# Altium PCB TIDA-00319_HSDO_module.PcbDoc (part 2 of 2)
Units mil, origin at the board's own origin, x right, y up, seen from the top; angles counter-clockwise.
Board outline 6250 x 2150 mil, 2 copper layers (Component Side, Bottom Layer), stack 12.8 mil thick; 90 components, 121 nets, 306 pads, 593 vias.
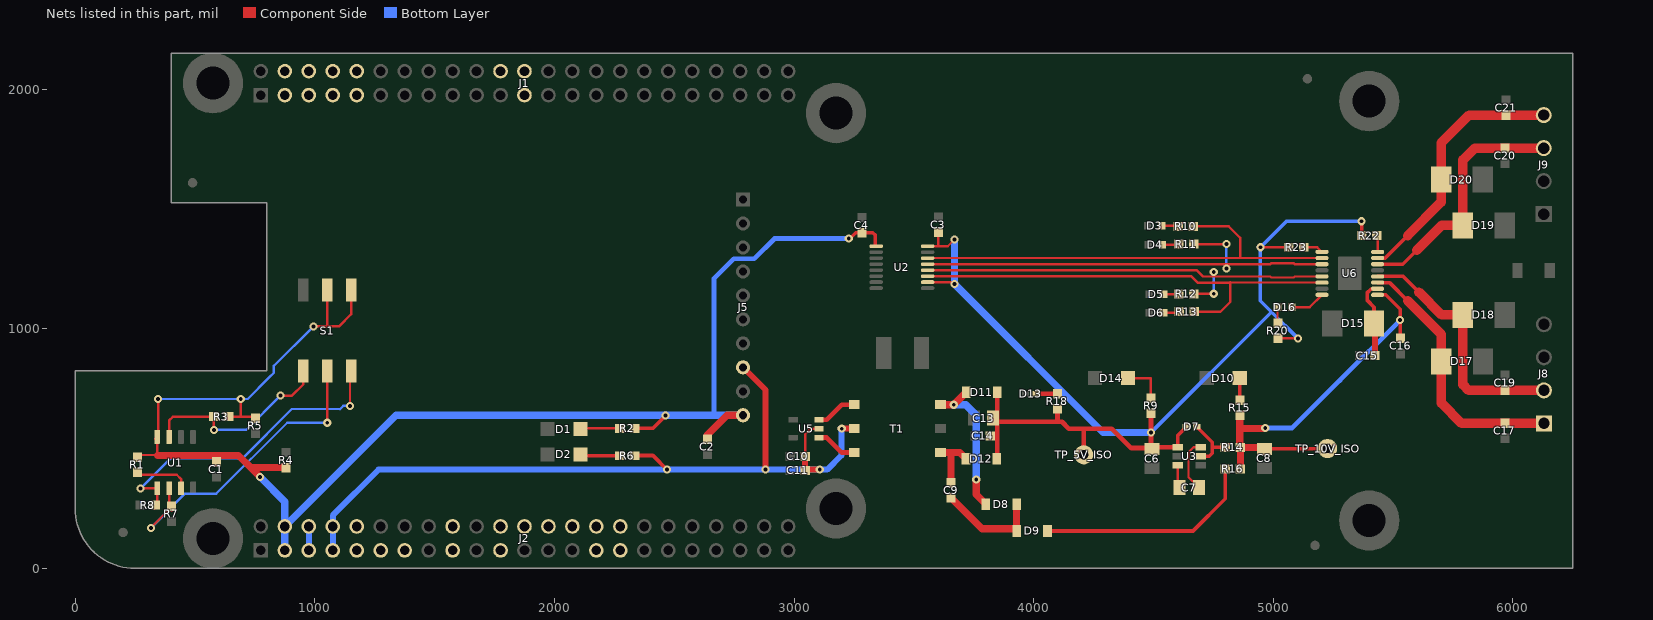
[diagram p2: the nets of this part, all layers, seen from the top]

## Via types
v1: diameter 20, hole 8, Component Side to Bottom Layer, tented both sides, 517 vias
v2: diameter 39.37, hole 19.68, Component Side to Bottom Layer, 36 vias
v3: diameter 34, hole 16, Component Side to Bottom Layer, 32 vias
v4: diameter 19.68, hole 7.87, Component Side to Bottom Layer, 6 vias
v5: diameter 50, hole 28, Component Side to Bottom Layer, 2 vias

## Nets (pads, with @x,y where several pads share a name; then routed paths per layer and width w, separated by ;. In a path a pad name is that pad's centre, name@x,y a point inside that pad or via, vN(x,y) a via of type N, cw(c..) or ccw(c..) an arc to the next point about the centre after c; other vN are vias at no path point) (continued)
MMC1_DAT1: J1.24
MMC1_DAT2: J1.5
MMC1_DAT3: J1.6
MMC1_DAT4: J1.23
MMC1_DAT5: J1.22
MMC1_DAT6: J1.3
MMC1_DAT7: J1.4
NetC7_1: C7.1 U3.6 | length 224.3
  Component Side w10: C7.1@4689,337 4646,380 4646,484.69 4666.72,505.4 U3.6@4696.24,505.4
NetC7_2: C7.2 U3.3 | length 96.6
  Component Side w10: U3.3@4601.76,430.6 4601.76,344.24 C7.2@4609,337
NetC9_1: C9.1 D8.1 D9.2 | length 443.3
  Component Side w30: C9.1@3655,294.5 3784.5,165 3919.53,165 D9.2@3928.53,156 3928.53,267.06 D8.1@3929.47,268
NetC15_1: C15.1 D15.1 U6.2 | length 325.2
  Component Side w15: D15.1@5420.01,1022 5420.01,1090.15 5392.58,1117.57 5392.58,1151.32 5406.56,1165.29 5424.55,1165.29 5426.28,1167.02 U6.2@5435.14,1167.02
  Component Side w25: D15.1@5420.01,1022 5423.5,1018.51 C15.1@5423.5,888
NetC17_1: C17.1 D17.1 J8.1 U6.3 | length 1105
  Component Side w15: U6.3@5435.14,1192.61 5484.39,1192.61 5561,1116
  Component Side w40: 5561,1116 5700.99,976.01 D17.1@5700.99,864 5700.99,690.01 5785.8,605.2 J8.1@6129.3,605.2
NetC19_1: C19.1 D18.1 J8.2 U6.4 | length 1061.5
  Component Side w15: U6.4@5435.14,1218.2 5541.8,1218.2 5607,1153
  Component Side w40: 5607,1153 5702,1058 D18.1@5790.99,1058 5790.99,767.01 5815,743 J8.2@6129.3,743
NetC20_1: C20.1 D19.1 J9.3 U6.6 | length 1053.7
  Component Side w15: U6.6@5435.14,1269.39 5540.39,1269.39 5598,1327
  Component Side w40: 5598,1327 5702,1431 D19.1@5790.99,1431 5790.99,1703.99 5840.8,1753.8 J9.3@6128.3,1753.8
NetC21_1: C21.1 D20.1 J9.4 U6.7 | length 1087.8
  Component Side w15: U6.7@5435.14,1294.98 5466.98,1294.98 5562,1390
  Component Side w40: 5560,1388 5699.99,1527.99 D20.1@5699.99,1622 5699.99,1774.99 5816.59,1891.59 J9.4@6128.3,1891.59
NetD1_2: D1.2 R2.1 | length 136.8
  Component Side w10: D1.2@2108.53,581.32 D1.2@2111.53,584.32 ; 2139.9,584 R2.1@2272.5,584
NetD2_2: D2.2 R6.1 | length 137.7
  Component Side w15: D2.2@2108.53,475.32 D2.2@2113.53,470.32 ; 2141.9,470 R6.1@2272.5,470
NetD3_1: D3.1 R10.1 | length 69.8
  Component Side w10: D3.1@4534.53,1429 4601.5,1429 R10.1@4603.5,1427
NetD4_1: D4.1 R11.1 | length 68.8
  Component Side w10: D4.1@4536.53,1351 4602.5,1351 R11.1@4604.5,1353
NetD5_1: D5.1 R12.1 | length 62.4
  Component Side w10: D5.1@4542.53,1144 4603.5,1144 R12.1@4604.5,1145
NetD6_1: D6.1 R13.1 | length 64.6
  Component Side w10: D6.1@4543.53,1067 4602.5,1067 R13.1@4606.5,1071
NetD7_1: D7.1 R14.1 U3.5 | length 246.3
  Component Side w15: D7.1@4680.65,591 4745,526.65 4745,506 ; U3.5@4696.24,468 4733,468 4745,480 4745,506 ; R14.1@4799.5,505 4746,505 4745,506
NetD9_1: D9.1 R16.1 | length 922.2
  Component Side w15: D9.1@4057.47,156 4665,156 4799.5,290.5 R16.1@4799.5,415
NetD10_2: D10.2 R15.1 | length 91.5
  Component Side w15: D10.2@4859.9,794 4860,793.9 R15.1@4860,702.5
NetD13_1: D13.1 R18.1 | length 89.6
  Component Side w20: D13.1@4009.65,729 4098.5,729 R18.1@4099,729.5
NetD14_2: D14.2 R9.1 | length 183.6
  Component Side w10: D14.2@4392.9,794 4489,794 R9.1@4489,706.5
NetD16_1: D16.1 R20.2 | length 68.1
  Component Side w10: D16.1@5017.47,1090 5017.47,1024.02 R20.2@5019,1022.5
NetD16_2: D16.2 U6.16 | length 147.6
  Component Side w10: D16.2@5076.53,1090 5151.43,1090 U6.16@5202.86,1141.43
NetR1_1: R1.1 U1.3 | length 211.2
  Component Side w10: R1.1@277.5,391 424,391 442,373 U1.3@442,333.72
NetR3_1: R3.1 S1.1 U1.7 | length 823.5
  Component Side w10: U1.7@392,548.28 392,617 408,633 R3.1@578.5,633 578.5,578.5 v3(579,578) ; v3(857,721) 905,721 952,768 S1.1@952,822.71
  Bottom Layer w10: v3(579,578) 714,578 v3(857,721)
NetR7_2: R7.2 S1.2 U1.2 | length 1336.9
  Component Side w10: v3@320,173.65 R7.2@395,248.65 ; U1.2@392,333.72 392,257.5 403,246.5 R7.2@403,241 ; v3(1052,608) S1.2@1052,822.71
  Bottom Layer w10: v3(316,168) 458,312 589,312 885,608 v3(1052,608)
NetR8_2: R8.2 S1.3 U1.1 | length 1319.7
  Component Side w10: v3(273.28,333.72) U1.1@342,333.72 342,261.5 R8.2@331.5,251 ; v3(1147,678) 1147,817.71 1150,820.71 S1.3@1152,822.71
  Bottom Layer w10: v3(273.28,333.72) 398.57,459 698,459 904,665 1104,665 1105,664 1119,678 v3(1147,678)
NetR22_1: R22.1 U6.8 | length 72.4
  Component Side w10: R22.1@5431.5,1388.98 5436.14,1384.34 U6.8@5436.14,1318.55
NetR23_1: R23.1 U6.9 | length 86.2
  Component Side w10: R23.1@5126.5,1339.98 5182.43,1339.98 U6.9@5203.86,1318.55
NetT1_1: T1.1 U5.3 | length 172.8
  Component Side w20: U5.3@3104.13,620.4 3136.4,620.4 3199,683 T1.1@3251,683
NetT1_3: T1.3 U5.1 | length 172.8
  Component Side w20: U5.1@3104.13,545.6 3136.6,545.6 3199.2,483 T1.3@3251,483
OUTA: R13.2 U2.11 U6.14 | length 1905
  Component Side w10: U2.11@3557.28,1219.5 4656.5,1219.5 4683.39,1192.61 4820,1192.61 4820,1112 4779,1071 R13.2@4669.5,1071 ; 4819.86,1193.23 U6.14@5202.86,1192.61
OUTB: R12.2 U2.12 U6.13 | length 1853.7
  Component Side w10: U2.12@3557.28,1244.5 4679.5,1244.5 4705.8,1218.2 4751,1218.2 ; R12.2@4667.5,1145 4668.5,1146 v3(4751,1146) ; v3(4751,1237) 4751,1218.2 ; U6.13@5202.86,1218.2 5089.33,1218.2 5085.13,1214 4991.28,1214 4987.08,1218.2 4751,1218.2
  Bottom Layer w10: v3(4751,1146) v3(4751,1237)
OUTC: R11.2 U2.13 U6.11 | length 1951.8
  Component Side w10: U2.13@3557.28,1269.5 4804,1269.5 v3(4804,1251) ; R11.2@4667.5,1364 4678.5,1353 v3(4804,1353) ; 4764.86,1269.48 4987.17,1269.48 4991.69,1274 5084.72,1274 5089.24,1269.48 U6.11@5203.36,1269.48 ; U6.11@5187.5,1267.48 5188,1266.98 U6.11@5188.39,1267.37
  Bottom Layer w10: v3(4804,1251) v3(4804,1353)
OUTD: R10.2 U2.14 U6.10 | length 1972.2
  Component Side w10: U2.14@3569.22,1295 4862,1295 4862,1379 4814,1427 R10.2@4666.5,1427 ; 4822.86,1294.98 U6.10@5202.86,1294.98
PWR_BUT: J2.9
SPI0_CS: J2.17
SPI0_D0: J2.21
SPI0_D1: J2.18
SPI0_SCLK: J2.22
SPI1_CS0: J2.28
SPI1_D0: J2.29
SPI1_D1: J2.30
SPI1_SCLK: J2.31
SYS_5V: C10.1 C11.1 J2.7 J2.8 J5.8 R6.2 T1.2 U5.2 | length 3449.7
  Component Side w10: C10.1@3046.5,467 3046.5,559.81 3069.69,583 U5.2@3104.13,583
  Component Side w15: R6.2@2335.5,470 2336.5,471 2411,471 v3(2470,412)
  Component Side w25: J5.8@2787,839 2881,745 v3(2881,412) ; C10.1@3046.5,467 C11.1@3046.5,409 3049.5,412 v3(3107,412) ; v3@3193,583 T1.2@3251,583
  Bottom Layer w15: v3(2470,412) v3@2480,412
  Bottom Layer w25: J2.7@1075,75 J2.8@1075,175 1075,221 1266,412 v3(2470,412) ; v3@2480,412 v3(2881,412) v3(3107,412) 3138,412 3198,472 3198,580 v3@3194,584
  other v3: 3199,583
SYS_RESETN: J2.10
TIMER4: J1.7
TIMER5: J1.9
TIMER6: J1.10
TIMER7: J1.8
TR_N: C9.2 D12.2 T1.4 | length 246.1
  Component Side w30: T1.4@3611,483 3663,483 ; C9.2@3655,357.5 3655,475 3663,483 ; D12.2@3717.53,457 3691.53,483 3663,483
TR_P: D8.2 D11.2 T1.6 | length 628.6
  Component Side w30: T1.6@3611,683 v3(3666.53,683) D11.2@3718.53,735 ; v3(3760,371) 3760,308.53 D8.2@3800.53,268
  Bottom Layer w30: v3(3666.53,683) 3716,683 3760,639 v3(3760,371)
UART1_RXD: J2.26
UART1_TXD: J2.24
UART4_RXD: J2.11
UART4_TXD: J2.13
VDD_3V3B: C1.1 C2.1 C4.2 J2.3 J2.4 J5.10 R1.2 R2.2 R3.2 R4.2 R5.2 S1.4 S1.5 U1.8 U2.1 | length 6509.9
  Component Side w10: R1.2@271,473 342,472.5 ; U1.8@334.22,540.5 U1.8@342,548.28 ; 343,471.5 342,472.5 ; v3(346,707) 346,552.28 U1.8@342,548.28 ; R3.2@641.5,633 691,633 ; v3(691,707) 691,633 ; R5.2@752,626.5 745.5,633 691,633 ; v3(994,1010) 1101,1010 1152,1061 S1.4@1152,1161.29 ; 1052,1016 S1.5@1052,1161.29 ; 342,472.5 U1.8@342,548.28
  Component Side w15: R2.2@2335.5,584 2410,584 v3(2464,638) ; v3(3228.29,1376.29) 3228.29,1371.71 3257.78,1401.2 C4.2@3282.57,1401.2 3328.8,1401.2 3338,1392 3338,1349.22 U2.1@3342.72,1344.5
  Component Side w30: 343,471.5 681.5,471.5 732.5,420.5 ; v3(771,382) 732.5,420.5 ; R4.2@880,420.5 732.5,420.5 ; C2.1@2636,554.5 2720.5,639 J5.10@2787,639
  Bottom Layer w10: v3(346,707) v3(691,707) 720,707 809,796 809.08,796 829,815.92 829,845 v3(994,1010)
  Bottom Layer w15: v3(2464,638) v3@2464,639
  Bottom Layer w20: 2666,639 2666,1210 2747.97,1291.97 2834.03,1291.97 2918.34,1376.29 v3(3228.29,1376.29)
  Bottom Layer w30: v3(771,382) 875,278 J2.4@875,175 ; J2.3@875,75 J2.4@875,175 ; J5.10@2787,639 2666,639 2464,639 1339,639 J2.4@875,175 ; v3(3228.29,1376.29) v3@3229.53,1376.31
VDD_5V: J2.5 J2.6 | length 100
  Bottom Layer w25: J2.5@975,75 J2.6@975,175
VDD_5V_ISO: C3.2 C6.1 C13.1 C14.1 D7.2 D11.1 D12.1 R9.2 R18.2 R20.1 R22.2 R23.2 TP_5V_ISO.1 U2.10 U2.16 U3.1 | length 4945.4
  Component Side w10: U2.10@3557.28,1194.5 3661.5,1194.5 v3(3670,1186) ; U2.16@3557.28,1344.5 3601,1344.5 ; C3.2@3602,1399 3602,1345.5 3601,1344.5 ; v3(3670,1373) 3641.5,1344.5 3601,1344.5 ; D12.1@3847.47,475 3848.47,474 D12.1@3851.5,470.96 ; v3(4946.02,1339.98) R23.2@5063.5,1339.98 ; R20.1@5019,959.5 v3(5102.5,959.5)
  Component Side w15: U3.1@4601.76,505.4 4601.76,555.41 D7.2@4637.35,591 ; R22.2@5368.5,1388.98 v3(5368.5,1448.5)
  Component Side w20: C13.1@3846,612 4099,612 ; D12.1@3846.47,457 3848.47,459 D12.1@3848.47,474 ; D12.1@3847.47,475 D11.1@3847.47,735 ; R18.2@4099,666.5 4099,612 ; 4117,612 4099,612 ; 4118,612 4147,583 4209,583 ; TP_5V_ISO.1@4209,474 4209,583 ; R9.2@4490,646.5 4490,566 C6.1@4490,505.4 ; C6.1@4494,498 C6.1@4490,502 ; U3.1@4601.76,505.4 C6.1@4490,505.4 ; 4209,583 4326,583 4407,502 C6.1@4490,502 ; C6.1@4490,502 C6.1@4490,505.4
  Component Side w30: v3(4489,567) v3@4490,566
  Bottom Layer w15: v3@4945,1341 4945,1117 4991,1071 v3(5102.5,959.5) ; v3(4946.02,1339.98) 5054.53,1448.5 v3(5368.5,1448.5)
  Bottom Layer w16: v3(4489,567) 4991,1069 4991,1071
  Bottom Layer w30: v3(3670,1373) v3(3670,1186) 4289,567 v3(4489,567) ; v3@4945,1341 v3(4946.02,1339.98)
VDD_10V_ISO: C8.1 C16.1 R14.2 R15.2 R16.2 TP_10V_ISO.1 U6.1 | length 1689.4
  Component Side w14: C16.1@5529,961.5 C16.1@5531,959.5 ; v3(5529,1036) 5529,1068
  Component Side w15: C8.1@4963,499 TP_10V_ISO.1@5225,499 ; U6.1@5435.14,1141.43 5468.57,1141.43 5529,1081 5529,1068 ; C16.1@5529,961.5 v3(5529,1036)
  Component Side w30: R15.2@4860,639.5 4860,584 ; R16.2@4862.5,415 R14.2@4862.5,505 ; C8.1@4963,499 4957,505 R14.2@4862.5,505 ; v3(4966,586) 4964,584 4860,584 ; TP_10V_ISO.1@5225,499 TP_10V_ISO.1@5226,500 ; 4860,584 4860,507.5 R14.2@4862.5,505
  Bottom Layer w20: v3(4966,586) 5079,586 5277.5,784.5 v3(5529,1036)
VDD_ADC: J2.32
pads on no net: FID1.1 FID2.1 FID4.1 FID5.1 MH1.1 MH2.1 MH3.1 MH4.1 MH5.1 MH6.1 U2.7 U6.15
copper on no net:
  other v2: 575,27.56 490.61,76.28 659.39,76.28 5400,102.56 5315.61,151.28 5484.39,151.28 3175,152.56 490.61,173.72 659.39,173.72 3090.61,201.28 3259.39,201.28 575,222.44 5315.61,248.72 5484.39,248.72 5400,297.44 3090.61,298.72 3259.39,298.72 3175,347.44 3175,1802.56 3090.61,1851.28 3259.39,1851.28 5400,1852.56 5315.61,1901.28 5484.39,1901.28 575,1927.56 3090.61,1948.72 3259.39,1948.72 490.61,1976.28 659.39,1976.28 3175,1997.44 5315.61,1998.72 5484.39,1998.72 5400,2047.44 490.61,2073.72 659.39,2073.72 575,2122.44

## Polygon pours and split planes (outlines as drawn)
DGND on Bottom Layer "Bottom Layer-DGND" (solid, remove dead copper, pour order 43): 20,2130 20,20 3370,20 3370,2130
GND_ISO on Bottom Layer "Bottom-GND_Signal" (solid, remove dead copper, pour order 59): 3540,0 3540,2150 6249.98,2150 6249.98,0
GND_ISO on Component Side "Top-GND_Signal" (solid, remove dead copper, pour order 60): 3540,0 3540,2150 6250,2150 6250,0
DGND on Component Side "DGND_TL" (solid, remove dead copper, pour order 81): 3370,2150 400,2150 0,2150 0,0 3370,0

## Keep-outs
Keep-Out Layer:
  lines w10: -5,825 -5,250 ccw(c250,250) 250,-5 6250,-5 ; 0,830 795,830 795,1520 400,1520 ; 6250,2155 400,2155 ; 6255,2150 6255,0 ; 395,1525 ccw(c400,1525) 400,1520 ; 395,1525 ccw(c400,1525) 400,1520 ; 395,1525 395,2150 ; 395,2150 cw(c400,2150) 400,2155 ; 395,2150 cw(c400,2150) 400,2155 ; 6250,-5 ccw(c6250,0) 6255,0 ; 6250,-5 ccw(c6250,0) 6255,0 ; 7517,2166 cw(c7517,2161) 7522,2161 ccw(c7517,2161) 7517,2166
  text ".Layer_Name" at 577,-858.49 h60

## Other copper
Component Side:
  rectangle net EARTH: 6096,1381.75 6201,1513
  rectangle net EARTH: 6095,984 6201,1113
  rectangle net EARTH: 6126,1082 6201,1407
  region net NetC15_1: 5385,1131.98 5385,1074 5427,1074
  text ".CopyrightYear" at 1455,1453 h60
  text ".Layer_Name" at 577,-858.49 h60
Bottom Layer:
  text ".Layer_Name" at 577,-858.49 h60

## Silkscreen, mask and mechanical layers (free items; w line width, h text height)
Top Overlay:
  region: 1397,1530 1097,1530 1097,1430 1397,1430
  lines w5: 5869,1509.5 5870,1510.5
  text "P8-Header" at 2140,1830 h40
  text ".PRJ_Number" at 892,1566 h60
  text ".PCB_Rev" at 912,1459 h60
  text "-" at 1029,1453 h60
  text "In4" at 2598,1418 h60
  text "OUT4" at 4137,1406 h60
  text "OUT3" at 4137,1340 h60
  text "In3" at 2598,1327 h60
  text "WR" at 892,1237 h30
  text "A1" at 1031,1235 h30
  text "A0" at 1172,1235 h30
  text "In2" at 2598,1129 h60
  text "OUT2" at 4137,1108 h60
  text "Fault" at 4834,1074 h60
  text "OUT1" at 4137,1039 h60
  text "In1" at 2598,1022 h60
  text "5V ISO" at 4195,868 h60
  text "10V ISO" at 4662,865 h60
  text "5V" at 2589,809 h60
  text "3.3V" at 2543,619 h60
  text "3.3V" at 1733.63,562.32 h40
  text "5V" at 1804.63,461.32 h40
  text "P9-Header" at 2140,260 h40
  text ".Layer_Name" at 577,-858.49 h60
Bottom Overlay:
  text ".Layer_Name" at 577,-858.49 h60
Top Paste:
  text ".Layer_Name" at 577,-858.49 h60
Bottom Paste:
  text ".Layer_Name" at 577,-858.49 h60
Top Solder:
  text ".Layer_Name" at 577,-858.49 h60
  text ".Layer_Name" at 577,-858.49 h60
Solder Side:
  text ".Layer_Name" at 577,-858.49 h60
Drill Guide:
  text ".Layer_Name" at 577,-858.49 h60
M1 Board Outline:
  the board outline again, w10
  text ".Layer_Name" at 577,-858.49 h60
M2 Board Dimensions:
  rectangle: 0,-285.5 125,-160.5
  rectangle: 125,-410.5 500,-285.5
  lines w7: 0,-285.5 1000,-285.5 ; 125,-410.5 125,-160.5 ; 250,-410.5 250,-160.5 ; 500,-410.5 500,-160.5 ; 750,-410.5 750,-160.5 ; 0,-410.5 1000,-410.5 1000,-160.5 0,-160.5 0,-410.5
  text ".Layer_Name" at 577,-858.49 h60
M3 3D STEP Top:
  pour cut-out: 4944,1600 5366,1600 5366,1754 4944,1754
  text ".Layer_Name" at 577,-858.49 h60
M4 3D STEP Bottom:
  text ".Layer_Name" at 577,-858.49 h60
M5 Assembly Top:
  lines w10: -292,-930.17 6308,-930.17 ; -292,-726.83 6310,-726.83 ; -292,-523.5 -292,-1133.5 3713,-1133.5 6310,-1133.5 6310,-523.5 -291.5,-523.5 -291.5,-1133.5 1284,-1133.5 ; 2173,-1133.5 2173,-523.5 ; 3440,-726.83 3440,-523.5 ; 4280,-726.83 4280,-523.5 ; 4902,-1140 4902,-937.17
  text "COMPONENTS MARKED 'DNP' SHOULD NOT BE POPULATED." at 1153.5,-318.5 h60
  text "ASSEMBLY VARIANT:" at 1153,-434 h60
  text ".VariantName" at 2189,-434 h60
  text "PCB VIEWED FROM TOP SIDE" at -228.5,-655.67 h60
  text "BOARD #:" at 2248,-655.67 h60
  text ".PRJ_Number" at 2793.5,-655.67 h60
  text "REV:" at 3638,-655.67 h60
  text ".PCB_Rev" at 3929.5,-655.67 h60
  text "SVN REV:" at 4476,-655.67 h60
  text ".VersionControl_RevNumber" at 4982,-655.67 h60
  text "IGNORE ->" at -228.5,-858.49 h60
  text "PLOT NAME =" at -228.5,-1064.34 h60
  text ".plot_File_Name" at 577,-1064.34 h60
  text "GENERATED    :" at 2250,-1064.34 h60
  text ".Print_Date" at 3119.5,-1064.34 h60
  text ".Print_Time" at 3848.5,-1064.34 h60
  text "TEXAS INSTRUMENTS" at 5113,-1064.34 h60
M6 Assembly Bottom:
  lines w10: -292.5,-727.33 6309.5,-727.33 ; -290.5,-930.67 6309.5,-930.67 ; 1115.5,-1140.5 1115.5,-937.67 ; 1737.5,-727.33 1737.5,-524 ; 2577.5,-727.33 2577.5,-524 ; 3844.5,-1134 3844.5,-524 ; 4733.5,-1134 6309,-1134 6309,-524 -292.5,-524 -292.5,-1134 2304.5,-1134 6309.5,-1134 6309.5,-524
  text "COMPONENTS MARKED 'DNP' SHOULD NOT BE POPULATED." at 6102,-318 h60
  text ".VariantName" at 5058,-434 h60
  text "ASSEMBLY VARIANT:" at 6097,-434 h60
  text ".VersionControl_RevNumber" at 1035.5,-656.17 h60
  text "SVN REV:" at 1541.5,-656.17 h60
  text ".PCB_Rev" at 2088,-656.17 h60
  text "REV:" at 2379.5,-656.17 h60
  text ".PRJ_Number" at 3224,-656.17 h60
  text "BOARD #:" at 3769.5,-656.17 h60
  text "PCB VIEWED FROM BOTTOM SIDE" at 6246,-656.17 h60
  text "IGNORE ->" at 2547.85,-858.49 h60
  text "TEXAS INSTRUMENTS" at 904.5,-1064.84 h60
  text ".Print_Time" at 2169,-1064.84 h60
  text ".Print_Date" at 2898,-1064.84 h60
  text "GENERATED    :" at 3767.5,-1064.84 h60
  text ".plot_File_Name" at 5440.5,-1064.84 h60
  text "PLOT NAME =" at 6246,-1064.84 h60
M9 Title Sheet:
  drawing of 57 lines, arcs and shapes, not listed
  text "1" at 739.84,8036.5 h70
  text "2" at 3235.5,8036.5 h70
  text "3" at 5724.84,8036.5 h70
  text "4" at 8231.51,8036.5 h70
  text "5" at 10730.5,8036.5 h70
  text "6" at 13235.5,8036.5 h70
  text "A" at -416.5,6893.5 h70
  text "A" at 14383.5,6893.5 h70
  text "B" at -416.5,4513.5 h70
  text "B" at 14383.5,4513.5 h70
  text "C" at -416.5,2138.5 h70
  text "C" at 14383.5,2138.5 h70
  text "PROJECT TITLE:" at 11343.5,277.5 h45
  text ".PRJ_Title" at 11393.5,144.17 h70
  text "DESIGNED FOR:" at 11343.5,-23.5 h45
  text ".PRJ_Customer" at 11393.5,-163.5 h70
  text "D" at -416.5,-231.5 h70
  text "D" at 14383.5,-231.5 h70
  text "FILE NAME:" at 11343.5,-323.5 h45
  text ".PCB_File_Name_No_Path" at 11393.5,-443.5 h70
  text "Texas Instruments (TI) and/or its licensors do not warrant the accuracy or completeness of this specification" at 6374,-605.34 h45
  text "ENGINEER:" at 11343.5,-613.5 h45
  text "LAYOUT BY:" at 12848.5,-613.5 h45
  text "or any information contained therein. TI and/or its licensors do not warrant that this design will meet" at 6329.01,-718 h45
  text ".PRJ_Engineer" at 11393.5,-768.49 h70
  text ".PCB_Layout" at 12899,-768.49 h70
  text "the specifications, will be suitable for your application or fit for any particular purpose, or will operate in" at 6329.01,-830.67 h45
  text ".Layer_Name" at 577,-858.49 h60
  text "ALTIUM DESIGNER VERSION:" at 12848.5,-923.5 h45
  text "an implementation. TI and/or its licensors do not warrant that the design is production worthy. You should" at 6329.01,-943.33 h45
  text "completely validate and test your design implementation to confirm the system functionality for your application." at 6374,-1056 h45
  text ".print_Scale" at 11393.5,-1056.83 h70
  text ".Application_BuildNumber" at 12899,-1056.83 h70
  text "1" at 739.84,-1263.5 h70
  text "2" at 3235.5,-1263.5 h70
  text "3" at 5724.84,-1263.5 h70
  text "4" at 8231.51,-1263.5 h70
  text "5" at 10730.5,-1263.5 h70
  text "6" at 13235.5,-1263.5 h70
M10 Fab Notes:
  drawing of 185 lines, arcs and shapes, not listed
  text "DESIGN INFORMATION" at 12381.02,5910 h60
  text "MIN. TRACK WIDTH:" at 11736.46,5730 h60
  text "8" at 12832.7,5730 h60
  text "MIL" at 12987.46,5730 h60
  text "MIN. CLEARANCE:" at 11736.46,5598 h60
  text "0.2" at 12772.7,5598 h60
  text "mm" at 12987.46,5598 h60
  text "MIN. VIA PAD SIZE:" at 11736.46,5466 h60
  text "24" at 12802.71,5466 h60
  text "MIL" at 12987.46,5466 h60
  text "0.05mm (2MIL)" at 12431.46,5324.29 h60
  text "MINIMUM ANNULAR RING" at 11407.23,5320 h60
  text "EXTERNAL" at 13139.46,5320 h60
  text "PER" at 11607.23,5202 h60
  text "IPC-D-275 CLASS 2 LEVEL C" at 11827.23,5202 h60
  text "MIL, HOLES" at 13315.46,5089.71 h60
  text "+/-" at 12923,5089 h60
  text "+/-" at 13777,5089 h60
  text "REGISTRATION TOLERANCES:" at 11407.23,5084 h60
  text "METAL" at 12607,5084 h60
  text "5" at 13183.2,5084 h60
  text "3" at 14016.2,5084 h60
  text "MIL" at 14132.46,5084 h60
  text "MATERIAL:" at 11332.46,4874.54 h60
  text "FR-4 High Tg" at 12318.9,4734.21 h60
  text "FR-408" at 11753.46,4725.64 h60
  text "X" at 12165.46,4725.64 h60
  text "OTHER" at 13241.46,4725.64 h60
  text "62 MIL (1.6mm) +/-10%" at 12073.56,4562.92 h60
  text "THICKNESS:" at 11407.23,4558.64 h60
  text "X" at 11945.4,4558.64 h60
  text "OTHER" at 13358.46,4558.64 h60
  text "TOLERANCE:" at 11407.23,4400.64 h60
  text "X" at 12246.53,4400.64 h60
  text "ANSI IPC-6012 TYPE 3 CLASS 2" at 12433.48,4400.64 h60
  text "OTHER +/-" at 12433.46,4244.64 h60
  text "BOW & TWIST:" at 11407.23,4087.64 h60
  text "X" at 12246.53,4087.64 h60
  text "ANSI IPC-6012 TYPE 3 CLASS 2" at 12433.48,4087.64 h60
  text "OTHER +/-" at 12433.46,3929.13 h60
  text "DRILLING:" at 11332.46,3790.64 h60
  text "REFERENCE:" at 11407.23,3673.64 h60
  text "X" at 12055.46,3673.64 h60
  text "AS SHOWN" at 12242.46,3673.64 h60
  text "X" at 12956.46,3673.64 h60
  text "NC_DRILL FILES" at 13093.46,3673.64 h60
  text "PTH MIN COPPER THICKNESS:" at 11407.23,3515.64 h60
  text "X" at 12757.46,3515.64 h60
  text "1MIL" at 12894.46,3515.64 h60
  text "OTHER" at 13391.46,3515.64 h60
  text "BOARD FINISH:" at 11332.46,3356.64 h60
  text "SILKSCREEN:" at 11487.68,3238.64 h60
  text "X" at 12436.46,3238.64 h60
  text "TOP" at 12562.46,3238.64 h60
  text "X" at 12946.46,3238.64 h60
  text "BOTTOM" at 13073.46,3238.64 h60
  text "SILKSCREEN COLOR:" at 11487.68,3071.64 h60
  text "X" at 12435.42,3071.64 h60
  text "WHITE" at 12562.46,3071.64 h60
  text "OTHER" at 13073.46,3071.64 h60
  text "SOLDER RESIST COLOR:" at 11487.68,2901.64 h60
  text "X" at 12055.42,2742.44 h60
  text "GREEN" at 12182.46,2742.44 h60
  text "BLUE" at 12773.46,2742.44 h60
  text "OTHER" at 13311.46,2742.44 h60
  text "IMMERSION GOLD (ENIG)" at 12393.46,2553.92 h60
  text "ENEPIG" at 13731,2550.64 h60
  text "SURFACE FINISH:" at 11332.46,2549.64 h60
  text "X" at 12206.51,2549.64 h60
  text "IMM. TIN/SILVER OR EQUIV" at 11662,2392.64 h60
  text "OTHER" at 13093.46,2392.64 h60
  text "ARRAY/PANEL:" at 11332.46,2213.64 h60
  text "CUT AND TRIM PER MECH LAYER 1" at 12393.46,2209.35 h60
  text "N.C. ROUTE" at 12393.46,2057.64 h60
  text "X" at 13072.46,2057.64 h60
  text "V. SCORE" at 13259.46,2057.64 h60
  text "CERTIFICATION:" at 11332.46,1920.64 h60
  text "MATERIALS AND WORKMANSHIP FOR ALL PCBS" at 12057.46,1920.64 h60
  text "TO MEET OR EXCEED THE REQUIREMENTS OF:" at 12057.46,1822.64 h60
  text "X" at 11683.96,1686.13 h60
  text "ANSI IPC-A-600F CLASS ->" at 11822.96,1686.13 h60
  text "X" at 13462.02,1686.13 h60
  text "2" at 13580.96,1686.14 h60
  text "1" at 13265.96,1684.64 h60
  text "3" at 13934.96,1684.64 h60
  text "X" at 11686.02,1526.64 h60
  text "UL 94V-0" at 11822.96,1526.64 h60
  text "X" at 12498.02,1526.64 h60
  text "RoHS" at 12634.96,1526.64 h60
  text "OTHER" at 13279.36,1526.64 h60
  text "PER ORDER" at 13676.42,1526.64 h60
  text "ADDITIONAL REQUIREMENTS:" at 11332.46,1385.64 h60
  text "MICROSECTION:" at 11407.23,1270.64 h60
  text "YES" at 12312.96,1270.64 h60
  text "REQUIRED" at 13174.46,1114.49 h60
  text "BARE BOARD ELEC. TEST:" at 11407.23,1111.64 h60
  text "NONE" at 12712.96,1111.64 h60
  text "X" at 13047.46,1111.64 h60
  text "PER ORDER" at 13766.46,1111.64 h60
  text "MANUFACTURER'S UL:" at 11407.23,954.64 h60
  text "RAIL" at 12572.96,950.35 h60
  text "METAL" at 13064.77,950.35 h60
  text "X" at 13440,950 h60
  text "SILK" at 13576.46,950.35 h60
  text ".Layer_Name" at 577,-858.49 h60
M11 Gerber Information:
  lines w10: -292,-930.17 6308,-930.17 ; -292,-726.83 6310,-726.83 ; -292,-523.5 -292,-1133.5 3713,-1133.5 6310,-1133.5 6310,-523.5 -291.5,-523.5 -291.5,-1133.5 1284,-1133.5 ; 2173,-1133.5 2173,-523.5 ; 3440,-726.83 3440,-523.5 ; 4280,-726.83 4280,-523.5 ; 4902,-1140 4902,-937.17
  text "ALL ARTWORK VIEWED FROM TOP SIDE" at -228.5,-655.67 h60
  text "BOARD #:" at 2248,-655.67 h60
  text ".PRJ_Number" at 2793.5,-655.67 h60
  text "REV:" at 3638,-655.67 h60
  text ".PCB_Rev" at 3929.5,-655.67 h60
  text "SVN REV:" at 4476,-655.67 h60
  text ".VersionControl_RevNumber" at 4982,-655.67 h60
  text "LAYER NAME =" at -228.5,-858.49 h60
  text "PLOT NAME =" at -228.5,-1064.34 h60
  text ".plot_File_Name" at 577,-1064.34 h60
  text "GENERATED    :" at 2250,-1064.34 h60
  text ".Print_Date" at 3119.5,-1064.34 h60
  text ".Print_Time" at 3848.5,-1064.34 h60
  text "TEXAS INSTRUMENTS" at 5113,-1064.34 h60
M12 Stackup:
  lines w6: 11360,7460 13910,7460 ; 11360,7564.4 13910,7564.4 ; 11300,6975 ccw(c11334,6975) 11334,6941 13936,6941 ccw(c13936,6975) 13970,6975 13970,7681 ccw(c13936,7681) 13936,7715 11334,7715 ccw(c11334,7681) 11300,7681 11300,6975
  text "The Stackup Legend below this is static." at 11605.5,7874.5 h60
  text "If you change the stackup, update the Legend." at 11615.5,7784.5 h60
  text "Layer Stack Up Detail for: Ref_Design.PcbDoc" at 11360,7597.1 h57
  text "Layer" at 11360,7525.4 h24
  text "Gerber" at 12255.81,7525.4 h24
  text "Copper" at 12819.33,7525.4 h24
  text "Dielectric" at 13422.04,7525.4 h24
  text "Name" at 11360,7477.4 h24
  text "Document" at 12255.81,7477.4 h24
  text "Thickness" at 12819.33,7477.4 h24
  text "Material" at 13422.04,7477.4 h24
  text "Top Solder Mask" at 11360,7384.44 h34
  text "(.GTS)" at 12255.81,7384.44 h34
  text "Solder Resist" at 13422.04,7384.44 h34
  text "Top Layer" at 11360,7287.69 h34
  text "(.GTL)" at 12255.81,7287.69 h34
  text "1.4mil" at 12819.33,7287.69 h34
  text "FR-4" at 13422.04,7239.31 h34
  text "Bottom Layer" at 11360,7190.94 h34
  text "(.GBL)" at 12255.81,7190.94 h34
  text "1.4mil" at 12819.33,7190.94 h34
  text "Bottom Solder Mask" at 11360,7094.19 h34
  text "(.GBS)" at 12255.81,7094.19 h34
  text "Solder Resist" at 13422.04,7094.19 h34
  text ".Layer_Name" at 577,-858.49 h60
M13 Component Bodies Top:
  text ".Layer_Name" at 577,-858.49 h60
M14 Component Bodies Bottom:
  text ".Layer_Name" at 577,-858.49 h60
M15 Courtyards Top:
  text ".Layer_Name" at 577,-858.49 h60
M16 Courtyards Bottom:
  text ".Layer_Name" at 577,-858.49 h60
Drill Drawing:
  text "Drill Table" at 10408,194 h60
  text ".Layer_Name" at 577,-858.49 h60

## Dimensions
0,0 to 0,2150 on M2 Board Dimensions
0,-410.5 to 1000,-410.5 on M2 Board Dimensions
6250,0 to 0,0 on M2 Board Dimensions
